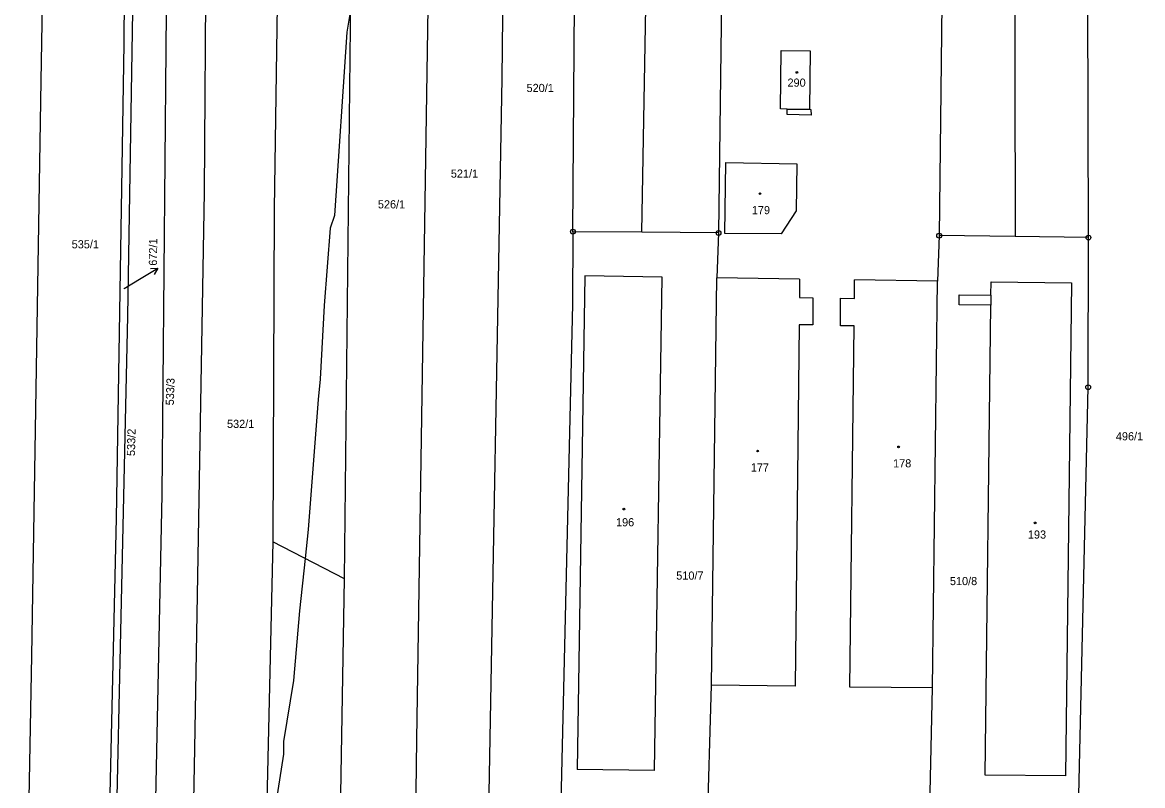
# Model space of a CAD drawing. Extents: x -747333 to -745433, y -1133152 to -1130600.
# Drawn here: x -746635.2 to -746401.5, y -1132600.8 to -1132441.6 of the extents above; entities that cross this region are included whole.
import ezdxf

# ---------------------------------------------------------------- set-up
doc = ezdxf.new("R2010")
doc.units = 0
for name, color, linetype in [('Vrstva 1', 7, 'Continuous'), ('Vrstva 16', 7, 'Continuous'), ('Vrstva 18', 7, 'Continuous'), ('Vrstva 19', 7, 'Continuous'), ('Vrstva 24', 7, 'Continuous'), ('Vrstva 25', 7, 'Continuous'), ('Vrstva 3', 7, 'Continuous'), ('Vrstva 37', 7, 'Continuous'), ('Vrstva 4', 7, 'Continuous'), ('Vrstva 52', 7, 'Continuous'), ('Vrstva 6', 7, 'Continuous')]:
    doc.layers.add(name, color=color, linetype=linetype)

msp = doc.modelspace()

# ---------------------------------------------------------------- linework, layer by layer
at = {"layer": 'Vrstva 1'}
for p, q in [((-746443.39, -1132437.7), (-746443.96, -1132486.07)), ((-746477.09, -1132459.62), (-746476.95, -1132447.46)), ((-746476.95, -1132447.46), (-746470.9, -1132447.53)), ((-746470.9, -1132447.53), (-746471.04, -1132459.69)), ((-746475.68, -1132459.65), (-746477.09, -1132459.62)), ((-746475.69, -1132460.82), (-746475.68, -1132459.65)), ((-746471.04, -1132459.69), (-746470.74, -1132459.72)), ((-746470.74, -1132459.72), (-746470.7, -1132460.94)), ((-746470.7, -1132460.94), (-746475.69, -1132460.82))]:
    msp.add_line(p, q, dxfattribs=at)
for points in [[(-746487.9, -1132322.49), (-746489.99, -1132485.51)], [(-746613.37, -1132346.68), (-746614.08, -1132446.06)], [(-746613.21, -1132502.87), (-746611.08, -1132371.37)], [(-746614.08, -1132446.06), (-746615.66, -1132545)], [(-746488.65, -1132485.59), (-746488.48, -1132470.84)], [(-746488.48, -1132470.84), (-746473.64, -1132471.05)], [(-746473.64, -1132471.05), (-746473.77, -1132480.86)], [(-746473.77, -1132480.86), (-746476.94, -1132485.69)], [(-746520.37, -1132485.24), (-746520.49, -1132500.34)], [(-746506, -1132485.37), (-746520.37, -1132485.24)], [(-746489.99, -1132485.51), (-746506, -1132485.37)], [(-746489.99, -1132485.51), (-746490.36, -1132494.89)], [(-746476.94, -1132485.69), (-746488.65, -1132485.59)], [(-746443.96, -1132486.07), (-746444.3, -1132495.53)], [(-746428.08, -1132486.27), (-746443.96, -1132486.07)], [(-746412.82, -1132486.47), (-746428.08, -1132486.27)], [(-746412.87, -1132517.7), (-746412.82, -1132486.47)], [(-746517.87, -1132494.47), (-746519.46, -1132597.46)], [(-746501.74, -1132494.74), (-746517.87, -1132494.47)], [(-746503.32, -1132597.69), (-746501.74, -1132494.74)], [(-746491.44, -1132579.84), (-746490.36, -1132494.89)], [(-746473.07, -1132495.14), (-746490.36, -1132494.89)], [(-746473.07, -1132495.14), (-746473.11, -1132499)], [(-746461.63, -1132499.17), (-746461.6, -1132495.32)], [(-746444.3, -1132495.53), (-746461.6, -1132495.32)], [(-746445.35, -1132580.44), (-746444.3, -1132495.53)], [(-746433.17, -1132498.48), (-746433.14, -1132495.69)], [(-746433.14, -1132495.69), (-746416.34, -1132495.88)], [(-746416.34, -1132495.88), (-746417.62, -1132598.8)], [(-746473.11, -1132499), (-746470.29, -1132499.03)], [(-746470.29, -1132499.03), (-746470.3, -1132504.71)], [(-746464.56, -1132504.89), (-746464.54, -1132499.14)], [(-746464.54, -1132499.14), (-746461.63, -1132499.17)], [(-746439.79, -1132500.49), (-746439.8, -1132498.4)], [(-746439.8, -1132498.4), (-746433.17, -1132498.48)], [(-746520.49, -1132500.34), (-746523.05, -1132610.33)], [(-746433.2, -1132500.57), (-746439.79, -1132500.49)], [(-746434.38, -1132598.64), (-746433.2, -1132500.57)], [(-746617.07, -1132675.21), (-746613.21, -1132502.87)], [(-746473.18, -1132504.68), (-746474.02, -1132580.06)], [(-746470.3, -1132504.71), (-746473.18, -1132504.68)], [(-746461.68, -1132504.91), (-746464.56, -1132504.89)], [(-746462.63, -1132580.24), (-746461.68, -1132504.91)], [(-746415.02, -1132611.93), (-746412.87, -1132517.7)], [(-746615.66, -1132545), (-746618.65, -1132675.35)], [(-746492.38, -1132610.98), (-746491.44, -1132579.84)], [(-746474.02, -1132580.06), (-746491.44, -1132579.84)], [(-746445.35, -1132580.44), (-746462.63, -1132580.24)], [(-746446.07, -1132611.66), (-746445.35, -1132580.44)], [(-746503.32, -1132597.69), (-746519.46, -1132597.46)], [(-746417.62, -1132598.8), (-746434.38, -1132598.64)]]:
    msp.add_lwpolyline(points, dxfattribs=at)
at = {"layer": 'Vrstva 16'}
msp.add_line((-746608.486965, -1132492.911756), (-746606.98644, -1132492.881368), dxfattribs=at)
for points in [[(-746610.41, -1132494.95), (-746606.98644, -1132492.881368), (-746607.711229, -1132494.195591)], [(-746613.98, -1132497.11), (-746610.41, -1132494.95)]]:
    msp.add_lwpolyline(points, dxfattribs=at)
at = {"layer": 'Vrstva 24'}
for p, q in [((-746520.42, -1132485.24), (-746520.32, -1132485.24)), ((-746490.04, -1132485.51), (-746489.94, -1132485.51)), ((-746444.01, -1132486.07), (-746443.91, -1132486.07)), ((-746412.87, -1132486.47), (-746412.77, -1132486.47)), ((-746412.92, -1132517.7), (-746412.82, -1132517.7))]:
    msp.add_line(p, q, dxfattribs=at)
for centre in [(-746520.37, -1132485.24), (-746489.99, -1132485.51), (-746443.96, -1132486.07), (-746412.82, -1132486.47), (-746412.87, -1132517.7)]:
    msp.add_circle(centre, 0.499289, dxfattribs=at)
at = {"layer": 'Vrstva 25'}
for centre in [(-746473.64, -1132452.02), (-746481.33, -1132477.3), (-746481.83, -1132531), (-746452.43, -1132530.14), (-746509.74, -1132543.13), (-746423.95, -1132545.99)]:
    msp.add_circle(centre, 0.174503, dxfattribs=at)
at = {"layer": 'Vrstva 3'}
for points in [[(-746477.09, -1132459.62), (-746476.95, -1132447.46)], [(-746476.95, -1132447.46), (-746470.9, -1132447.53)], [(-746470.9, -1132447.53), (-746471.04, -1132459.69)], [(-746475.68, -1132459.65), (-746477.09, -1132459.62)], [(-746475.68, -1132459.65), (-746471.04, -1132459.69)], [(-746488.65, -1132485.59), (-746488.48, -1132470.84)], [(-746488.48, -1132470.84), (-746473.64, -1132471.05)], [(-746473.64, -1132471.05), (-746473.77, -1132480.86)], [(-746473.77, -1132480.86), (-746476.94, -1132485.69)], [(-746476.94, -1132485.69), (-746488.65, -1132485.59)], [(-746517.87, -1132494.47), (-746519.46, -1132597.46)], [(-746501.74, -1132494.74), (-746517.87, -1132494.47)], [(-746503.32, -1132597.69), (-746501.74, -1132494.74)], [(-746491.44, -1132579.84), (-746490.36, -1132494.89)], [(-746473.07, -1132495.14), (-746490.36, -1132494.89)], [(-746473.07, -1132495.14), (-746473.11, -1132499)], [(-746461.63, -1132499.17), (-746461.6, -1132495.32)], [(-746444.3, -1132495.53), (-746461.6, -1132495.32)], [(-746445.35, -1132580.44), (-746444.3, -1132495.53)], [(-746433.17, -1132498.48), (-746433.14, -1132495.69)], [(-746433.14, -1132495.69), (-746416.34, -1132495.88)], [(-746416.34, -1132495.88), (-746417.62, -1132598.8)], [(-746473.11, -1132499), (-746470.29, -1132499.03)], [(-746470.29, -1132499.03), (-746470.3, -1132504.71)], [(-746464.56, -1132504.89), (-746464.54, -1132499.14)], [(-746464.54, -1132499.14), (-746461.63, -1132499.17)], [(-746433.17, -1132498.48), (-746433.2, -1132500.57)], [(-746434.38, -1132598.64), (-746433.2, -1132500.57)], [(-746473.18, -1132504.68), (-746474.02, -1132580.06)], [(-746470.3, -1132504.71), (-746473.18, -1132504.68)], [(-746461.68, -1132504.91), (-746464.56, -1132504.89)], [(-746462.63, -1132580.24), (-746461.68, -1132504.91)], [(-746474.02, -1132580.06), (-746491.44, -1132579.84)], [(-746445.35, -1132580.44), (-746462.63, -1132580.24)], [(-746503.32, -1132597.69), (-746519.46, -1132597.46)], [(-746417.62, -1132598.8), (-746434.38, -1132598.64)]]:
    msp.add_lwpolyline(points, dxfattribs=at)
at = {"layer": 'Vrstva 37'}
for centre in [(-746473.64, -1132452.02), (-746481.33, -1132477.3), (-746481.83, -1132531), (-746452.43, -1132530.14), (-746509.74, -1132543.13), (-746423.95, -1132545.99)]:
    msp.add_circle(centre, 0.174503, dxfattribs=at)
at = {"layer": 'Vrstva 4'}
msp.add_line((-746475.68, -1132459.65), (-746471.04, -1132459.69), dxfattribs=at)
msp.add_lwpolyline([(-746433.17, -1132498.48), (-746433.2, -1132500.57)], dxfattribs=at)
at = {"layer": 'Vrstva 52'}
msp.add_lwpolyline([(-746566.74, -1132439.03), (-746567.56, -1132443.63), (-746570.13, -1132481.87), (-746571, -1132484.5), (-746572.25, -1132500.63), (-746573.13, -1132516), (-746573.5, -1132520.25), (-746575.62, -1132547.37), (-746576.25, -1132553.43), (-746577.38, -1132564.38), (-746578.63, -1132578.87), (-746580.75, -1132591.62), (-746580.75, -1132594.25), (-746583.31, -1132610.75)], dxfattribs=at)
at = {"layer": 'Vrstva 6'}
for points in [[(-746631.28, -1132453.79), (-746628.68, -1132300.58)], [(-746506, -1132485.37), (-746503.02, -1132317.1)], [(-746580.99, -1132362.37), (-746582.7, -1132480.44)], [(-746597.26, -1132477.01), (-746596.54, -1132375.65)], [(-746535.13, -1132453.3), (-746534.4, -1132381.92)], [(-746520.37, -1132485.24), (-746519.81, -1132409.04)], [(-746412.82, -1132486.47), (-746413.02, -1132411.65)], [(-746428.24, -1132415.89), (-746428.08, -1132486.27)], [(-746605.1, -1132423.88), (-746606.11, -1132540.09)], [(-746568.01, -1132557.67), (-746566.71, -1132436.04)], [(-746552.94, -1132591.21), (-746550.51, -1132434.05)], [(-746633.28, -1132573.72), (-746631.28, -1132453.79)], [(-746537.98, -1132610.05), (-746535.13, -1132453.3)], [(-746599.26, -1132593.08), (-746597.26, -1132477.01)], [(-746582.7, -1132480.44), (-746582.99, -1132549.96)], [(-746606.11, -1132540.09), (-746608.92, -1132673.97)], [(-746582.99, -1132549.96), (-746585.75, -1132670.43)], [(-746568.01, -1132557.67), (-746582.99, -1132549.96)], [(-746569.62, -1132651.54), (-746568.01, -1132557.67)], [(-746635.22, -1132678.03), (-746633.28, -1132573.72)], [(-746553.66, -1132645.75), (-746552.94, -1132591.21)], [(-746600.75, -1132672.72), (-746599.26, -1132593.08)]]:
    msp.add_lwpolyline(points, dxfattribs=at)

# ---------------------------------------------------------------- texts
at = {"layer": 'Vrstva 16'}
msp.add_text('672/1', height=1.7, rotation=89.38917, dxfattribs=at).set_placement((-746607.15, -1132492.35))
at = {"layer": 'Vrstva 18'}
for s, height, p in [('520/1', 1.7, (-746530.04, -1132456.1)), ('521/1', 1.7, (-746545.84, -1132473.97)), ('526/1', 1.7, (-746561.06, -1132480.38)), ('535/1', 1.7, (-746624.94, -1132488.72)), ('672/1', 0.1, (-746614.153611, -1132497.11)), ('532/1', 1.7, (-746592.53, -1132526.19)), ('496/1', 1.7, (-746407.1, -1132528.78)), ('510/7', 1.7, (-746498.81, -1132557.84)), ('510/8', 1.7, (-746441.72, -1132558.98))]:
    msp.add_text(s, height=height, dxfattribs=at).set_placement(p)
for s, rotation, p in [('533/3', 88.12647, (-746603.64, -1132521.49)), ('533/2', 88.59438, (-746611.74, -1132532.06))]:
    msp.add_text(s, height=1.7, rotation=rotation, dxfattribs=at).set_placement(p)
at = {"layer": 'Vrstva 19'}
for s, p in [('290', (-746475.602407, -1132454.99)), ('179', (-746483.04, -1132481.59)), ('177', (-746483.26, -1132535.28)), ('178', (-746453.57, -1132534.42)), ('196', (-746511.38, -1132546.71)), ('193', (-746425.45, -1132549.28))]:
    msp.add_text(s, height=1.7, dxfattribs=at).set_placement(p)

doc.saveas('drawing.dxf')
